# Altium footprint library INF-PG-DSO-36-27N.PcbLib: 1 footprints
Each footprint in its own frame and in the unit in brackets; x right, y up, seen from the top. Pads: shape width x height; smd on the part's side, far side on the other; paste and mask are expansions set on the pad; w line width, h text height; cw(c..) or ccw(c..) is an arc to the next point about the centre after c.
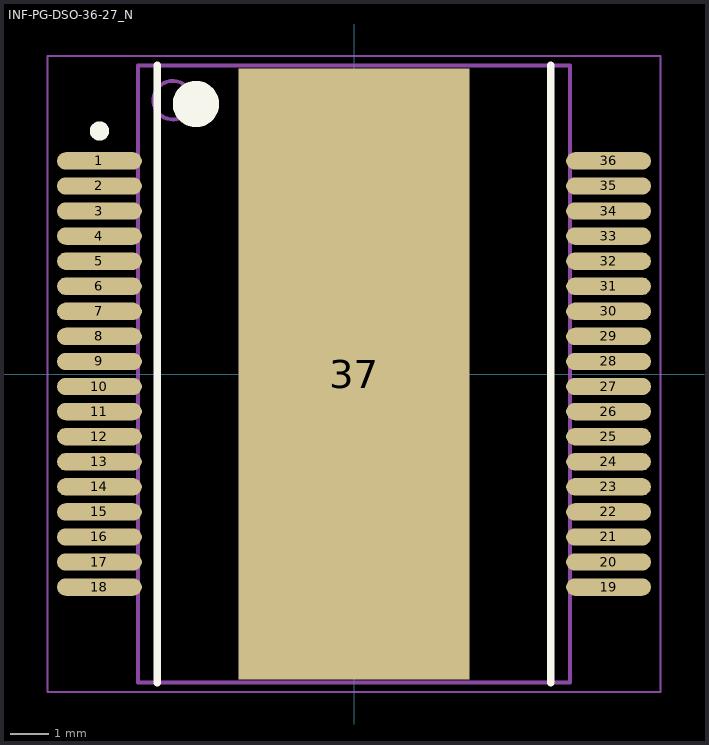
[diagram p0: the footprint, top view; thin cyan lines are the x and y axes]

## INF-PG-DSO-36-27_N [mm] "SOP, 36-Leads, Body 15.9x11mm, Pitch 0.65mm, Thermal Pad 15.84x6mm, IPC Medium Density"
height 3.5
pads (37):
  oval 2.2x0.45 smd: 1(-6.6,5.525) 2(-6.6,4.875) 3(-6.6,4.225) 4(-6.6,3.575) 5(-6.6,2.925) 6(-6.6,2.275) 7(-6.6,1.625) 8(-6.6,0.975) 9(-6.6,0.325) 10(-6.6,-0.325) 11(-6.6,-0.975) 12(-6.6,-1.625) 13(-6.6,-2.275) 14(-6.6,-2.925) 15(-6.6,-3.575) 16(-6.6,-4.225) 17(-6.6,-4.875) 18(-6.6,-5.525) 19(6.6,-5.525) 20(6.6,-4.875) 21(6.6,-4.225) 22(6.6,-3.575) 23(6.6,-2.925) 24(6.6,-2.275) 25(6.6,-1.625) 26(6.6,-0.975) 27(6.6,-0.325) 28(6.6,0.325) 29(6.6,0.975) 30(6.6,1.625) 31(6.6,2.275) 32(6.6,2.925) 33(6.6,3.575) 34(6.6,4.225) 35(6.6,4.875) 36(6.6,5.525)
  rect 6x15.84 smd: 37(0,0)
Top Overlay:
  circle w0.25: c-6.6,6.3 r0.125
  circle w0.6: c-4.1,7 r0.3
  lines w0.2: -5.1,-8 -5.1,8 ; 5.1,-8 5.1,8
Mechanical 13:
  circle w0.1: c-4.7,7.1 r0.5
  lines w0.1: -5.6,-8 -5.6,8 5.6,8 5.6,-8 -5.6,-8
Mechanical 15:
  lines w0.05: -7.95,-8.25 -7.95,8.25 7.95,8.25 7.95,-8.25 -7.95,-8.25
  lines w0.1: -0.5,0 0.5,0 ; 0,-0.5 0,0.5
3D body: height 3.5, standoff 0, extent -5.6,-8 5.6,8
